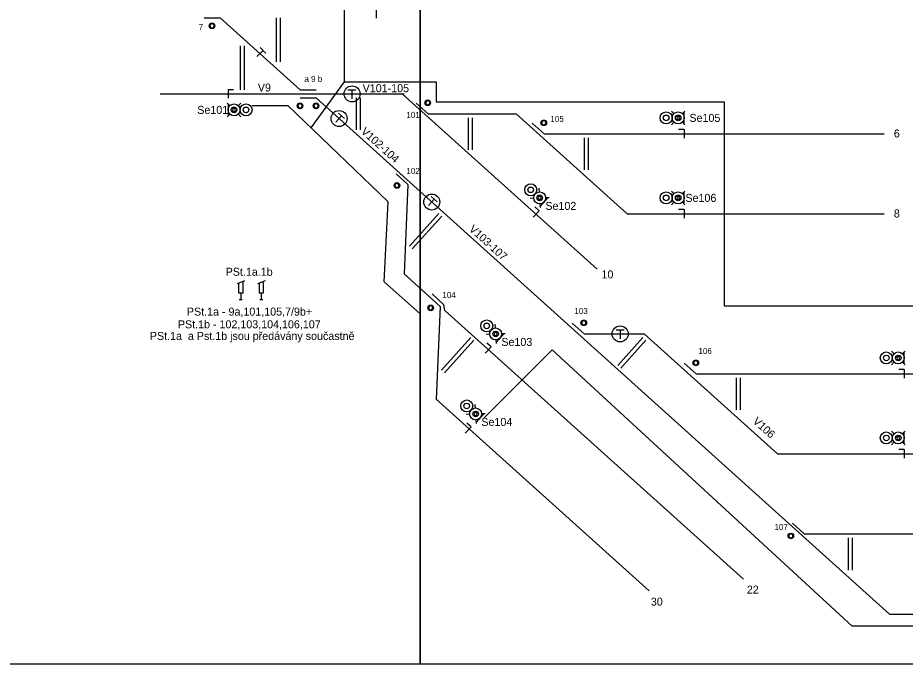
# Model space of a CAD drawing. Extents: x -1146 to 534, y 4 to 301.
# Drawn here: x -406.6 to -184.8, y 4.4 to 166 of the extents above; entities that cross this region are included whole.
import ezdxf

# ---------------------------------------------------------------- set-up
doc = ezdxf.new("R2010")
doc.units = 0
for name, color, linetype in [('formát tisku', 7, 'Continuous'), ('kabel', 7, 'Continuous'), ('koleje', 7, 'Continuous'), ('návěstidla', 7, 'Continuous'), ('popisy', 7, 'Continuous'), ('čd', 7, 'Continuous')]:
    doc.layers.add(name, color=color, linetype=linetype)

# ---------------------------------------------------------------- blocks, each defined once
blk = doc.blocks.new('NS1')
for p, q in [((-1, 2.5), (-1.7, 3.2)), ((1, 2.5), (1.7, 3.2)), ((-1, 0.5), (-1.7, -0.2)), ((-1.5, 0), (1.5, 0)), ((1, 0.5), (1.7, -0.2))]:
    blk.add_line(p, q)
for centre, radius in [((0, 4.5), 1.5), ((0, 4.5), 0.7), ((0, 1.5), 1.5)]:
    blk.add_circle(centre, radius)
for start, end in [(0, 180), (180, 0)]:
    blk.add_arc((0, 1.5), 0.375, start, end)
blk = doc.blocks.new('SB4')
for q in [(-1.39, 1.08), (0, -1.08)]:
    blk.add_line((0, 1.08), q)
blk = doc.blocks.new('SB1')
for p, q in [((0, 1.08), (-1, 1.08)), ((1, 1.08), (0, 1.08)), ((0, 1.08), (0, -1.08))]:
    blk.add_line(p, q)
blk = doc.blocks.new('SB2')
for p, q in [((-0.03, 0.94), (-1.03, 0.94)), ((0.96, 0.94), (-0.04, 0.94)), ((-0.03, 0.94), (-0.03, -1.21))]:
    blk.add_line(p, q)
blk.add_circle((0, 0), 2)
blk = doc.blocks.new('PZ2')
for start, end in [(0, 180), (180, 0)]:
    blk.add_arc((0, 2), 0.5, start, end)
blk = doc.blocks.new('O8')
for p, q in [((1.25, 6.25), (-1.25, 5.25)), ((0.75, 2.25), (0.75, 6.05)), ((-0.75, 5.45), (-0.75, 2.25)), ((-0.75, 2.25), (0.75, 2.25)), ((-0.5, 0), (0.5, 0)), ((0, 2.25), (0, 0))]:
    blk.add_line(p, q)

msp = doc.modelspace()

# ---------------------------------------------------------------- linework, layer by layer
for p, q in [((-345.26, 157.85), (-346.77, 156.31)), ((-345.26, 157.85), (-345.98, 158.55)), ((-344.55, 157.15), (-345.27, 157.85)), ((-305.96, 4.44), (-305.96, 13.33))]:
    msp.add_line(p, q)
for centre in [(-358, 164), (-336, 144), (-332, 144), (-304.09, 144.77), (-352.5, 143), (-275.09, 139.77), (-241.5, 141), (-311.79, 124.12), (-276.11, 121), (-241.5, 121), (-303.34, 93.51), (-265.09, 89.77), (-287.11, 87), (-237.09, 79.77), (-186.5, 81), (-292.11, 67), (-186.5, 61), (-213.34, 36.51)]:
    msp.add_circle(centre, 0.7)
at = {"layer": 'formát tisku'}
for points in [[(-515.96, 301.44), (-305.96, 301.44), (-305.96, 4.44), (-515.96, 4.44)], [(-305.96, 301.44), (-95.96, 301.44), (-95.96, 4.44), (-305.96, 4.44)]]:
    msp.add_lwpolyline(points, close=True, dxfattribs=at)
at = {"layer": 'kabel'}
for points in [[(-381, 195), (-355, 170), (-325, 170), (-325, 150), (-333.33, 138.55)], [(-325, 150), (-302, 150), (-302, 145), (-230, 145), (-230, 94), (-170, 94), (-170, 14), (-198, 14), (-273, 83), (-290, 66)], [(-306, 92), (-315, 100), (-314, 120), (-339, 144), (-348, 144)]]:
    msp.add_lwpolyline(points, dxfattribs=at)
at = {"layer": 'koleje'}
for p, q in [((-360, 166), (-356, 166)), ((-356, 166), (-336, 148)), ((-342, 166), (-342, 155)), ((-341, 166), (-341, 155)), ((-351, 159), (-351, 148)), ((-350, 159), (-350, 148)), ((-371, 147), (-310, 147)), ((-336, 148), (-332, 148)), ((-310.44, 147), (-261.73, 103.16)), ((-336, 146), (-332, 146)), ((-332, 146), (-188.67, 17)), ((-322, 146), (-322, 138)), ((-321, 146), (-321, 138)), ((-306.97, 144.68), (-304, 142)), ((-304, 142), (-282, 142)), ((-282, 142), (-254.22, 117)), ((-294, 141), (-294, 133)), ((-293, 141), (-293, 133)), ((-277.97, 139.68), (-275, 137)), ((-275, 137), (-190, 137)), ((-265, 136), (-265, 128)), ((-264, 136), (-264, 128)), ((-312, 127), (-309.03, 124.32)), ((-309.03, 124.32), (-310, 102)), ((-301.32, 117.09), (-308.68, 108.91)), ((-300.58, 116.42), (-307.94, 108.24)), ((-254.22, 117), (-190, 117)), ((-310, 102), (-300.96, 93.87)), ((-300.04, 94.31), (-303, 97)), ((-300.96, 93.87), (-301.97, 70.68)), ((-299.83, 92.85), (-300.04, 94.31)), ((-299.83, 92.85), (-225.2, 25.68)), ((-267.97, 89.68), (-265, 87)), ((-265, 87), (-250, 87)), ((-250, 87), (-216.67, 57)), ((-293.32, 86.09), (-300.68, 77.91)), ((-292.58, 85.42), (-299.94, 77.24)), ((-250.32, 86.09), (-256.59, 79.12)), ((-249.58, 85.42), (-255.85, 78.45)), ((-239.97, 79.68), (-237, 77)), ((-237, 77), (-160, 77)), ((-227, 76), (-227, 68)), ((-226, 76), (-226, 68)), ((-301.97, 70.68), (-248.78, 22.8)), ((-216.67, 57), (-160, 57)), ((-212.97, 39.68), (-210, 37)), ((-210, 37), (-160, 37)), ((-199, 36), (-199, 28)), ((-198, 36), (-198, 28)), ((-188.67, 17), (-160, 17))]:
    msp.add_line(p, q, dxfattribs=at)

# ---------------------------------------------------------------- block references
at = {"xscale": 0.7499999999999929, "yscale": 0.7499999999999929}
for p in [(-350.82, 95.61), (-345.68, 95.62)]:
    msp.add_blockref('O8', p, dxfattribs=at)
at = {"layer": 'návěstidla'}
for p, rotation in [((-354, 143), -89.99999999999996), ((-240, 141), 90.00000000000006), ((-275, 120), 48.01278750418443), ((-240, 121), 90.00000000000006), ((-286, 86), 48.01278750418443), ((-185, 81), 90.00000000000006), ((-291, 66), 48.01278750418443), ((-185, 61), 90.00000000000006)]:
    msp.add_blockref('NS1', p, dxfattribs=dict(at, rotation=rotation))
at = {"layer": 'čd'}
for name, p in [('SB1', (-317, 167)), ('SB2', (-323, 147)), ('SB4', (-240, 137)), ('SB4', (-240, 117)), ('SB2', (-256, 87)), ('SB4', (-185, 77)), ('SB4', (-185, 57))]:
    msp.add_blockref(name, p, dxfattribs=at)
for name, p, rotation in [('PZ2', (-358, 166), 180), ('PZ2', (-336, 146), 180), ('PZ2', (-332, 146), 180), ('PZ2', (-305.43, 143.28), -41.98721249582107), ('SB2', (-326.25, 140.82), -41.98721249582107), ('PZ2', (-276.43, 138.28), -41.98721249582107), ('PZ2', (-310.45, 125.61), 138.012787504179), ('SB2', (-303.07, 119.97), -41.98721249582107), ('SB4', (-277, 117), -41.987212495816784), ('PZ2', (-302, 95), 138.012787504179), ('PZ2', (-266.43, 88.28), -41.98721249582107), ('SB4', (-289, 83), -41.987212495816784), ('PZ2', (-238.43, 78.28), -41.98721249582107), ('SB4', (-294, 63), -41.987212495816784), ('PZ2', (-212, 38), 138.01278750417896)]:
    msp.add_blockref(name, p, dxfattribs=dict(at, rotation=rotation))
at = {"layer": 'čd', "yscale": -1, "rotation": 180}
msp.add_blockref('SB4', (-354, 147), dxfattribs=at)

# ---------------------------------------------------------------- texts
for s, height, p in [('7', 1.5, (-361.32, 163)), ('a 9 b', 1.5, (-334.92, 150)), ('101', 1.5, (-309.43, 141)), ('105', 1.5, (-273.43, 140)), ('102', 1.5, (-309.43, 127)), ('PSt.1a.1b', 2, (-354.59, 101.54)), ('104', 1.5, (-300.43, 96)), ('PSt.1a - 9a,101,105,7/9b+', 2, (-364.28, 91.58)), ('103', 1.5, (-267.43, 92)), ('PSt.1b - 102,103,104,106,107', 2, (-366.53, 88.41)), ('PSt.1a  a Pst.1b jsou předávány součastně', 2, (-373.54, 85.5)), ('106', 1.5, (-236.43, 82)), ('107', 1.5, (-217.43, 38))]:
    msp.add_text(s, height=height).set_placement(p)
at = {"layer": 'popisy'}
for s, p in [('V9', (-346.55, 147.58)), ('V101-105', (-320.36, 147.42)), ('Se101', (-361.69, 142)), ('Se105', (-238.69, 140)), ('6', (-187.6, 136.1)), ('Se106', (-239.69, 120)), ('Se102', (-274.69, 118)), ('8', (-187.6, 116.1)), ('10', (-260.67, 100.88)), ('Se103', (-285.69, 84)), ('Se104', (-290.69, 64)), ('22', (-224.33, 22.1)), ('30', (-248.33, 19.1))]:
    msp.add_text(s, height=2, dxfattribs=at).set_placement(p)
for s, p in [('V102-104', (-320.94, 137.36)), ('V103-107', (-293.94, 112.97)), ('V106', (-223.02, 64.94))]:
    msp.add_text(s, height=2, rotation=317.8973, dxfattribs=at).set_placement(p)

doc.saveas('drawing.dxf')
